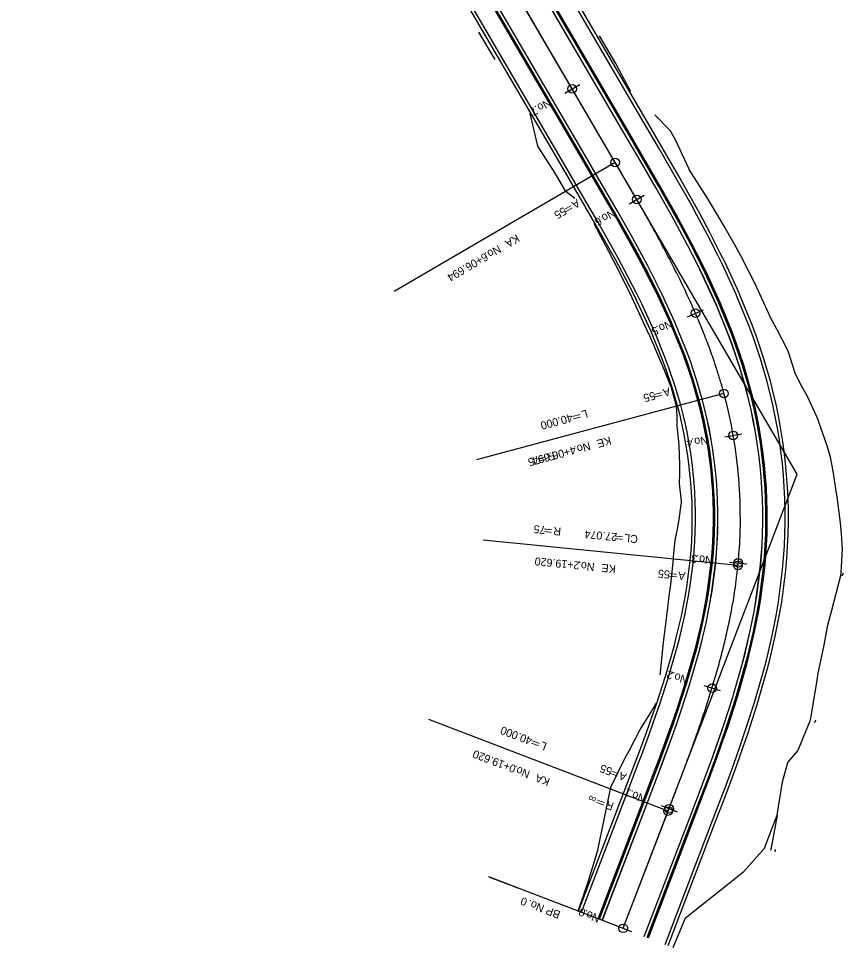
# Model space of a CAD drawing. Extents: x 46424 to 47578, y 10417 to 11548.
# Drawn here: x 46423.8 to 46552.6, y 10417.5 to 10562.5 of the extents above; entities that cross this region are included whole.
import ezdxf

# ---------------------------------------------------------------- set-up
doc = ezdxf.new("R2010")
doc.units = 0
for name, color, linetype in [('Default', 7, 'Continuous'), ('出典（地理院地図Vector）', 7, 'Continuous'), ('河川_人工水路(地下)（地理院地図Vector）', 7, 'Continuous'), ('現況_地形', 7, 'Continuous'), ('現況_地形_三角形', 7, 'Continuous'), ('現況_地形_三角形_頂点', 7, 'Continuous'), ('現況_地形_低い点', 7, 'Continuous'), ('現況_地形_単点標高', 7, 'Continuous'), ('現況_地形_等高線_マイナー', 7, 'Continuous'), ('等高線等深線_等高線_補助曲線通常部（地理院地図Vector）', 7, 'Continuous'), ('設計図面_測点 ラベル メジャー', 7, 'Continuous'), ('設計図面_測点 印 メジャー', 7, 'Continuous')]:
    doc.layers.add(name, color=color, linetype=linetype)

msp = doc.modelspace()

# ---------------------------------------------------------------- linework, layer by layer
at = {"layer": 'Default'}
for p, q in [((46516.96, 10540.04), (46459.34, 10638.67)), ((46510.25, 10551.53), (46510.25, 10551.53)), ((46516.96, 10540.04), (46482.42, 10519.86)), ((46516.96, 10540.04), (46516.96, 10540.04)), ((46520.32, 10534.25), (46520.32, 10534.25)), ((46529.49, 10516.49), (46529.49, 10516.49)), ((46533.94, 10503.96), (46495.3, 10493.6)), ((46533.94, 10503.96), (46495.3, 10493.6)), ((46533.94, 10503.96), (46533.94, 10503.96)), ((46535.38, 10497.42), (46535.38, 10497.42)), ((46536.13, 10477.12), (46496.33, 10481.07)), ((46536.13, 10477.12), (46496.33, 10481.07)), ((46536.13, 10477.12), (46536.13, 10477.12)), ((46536.17, 10477.5), (46536.17, 10477.5)), ((46532.08, 10457.96), (46532.08, 10457.96)), ((46525.23, 10438.76), (46487.88, 10453.07)), ((46525.37, 10439.12), (46525.37, 10439.12)), ((46518.22, 10420.44), (46525.23, 10438.76)), ((46525.23, 10438.76), (46525.23, 10438.76)), ((46517.59, 10420.68), (46497.21, 10428.49)), ((46497.21, 10428.49), (46501.88, 10426.7)), ((46518.22, 10420.44), (46518.22, 10420.44)), ((46518.22, 10420.44), (46518.22, 10420.44))]:
    msp.add_line(p, q, dxfattribs=at)
for centre in [(46510.25, 10551.53), (46516.96, 10540.04), (46520.32, 10534.25), (46529.49, 10516.49), (46533.94, 10503.96), (46535.38, 10497.42), (46536.17, 10477.5), (46536.13, 10477.12), (46532.08, 10457.96), (46525.23, 10438.76), (46525.37, 10439.12), (46518.22, 10420.44), (46518.22, 10420.44)]:
    msp.add_circle(centre, 0.675, dxfattribs=at)
msp.add_arc((46461.5, 10484.53), 75, 354.3288, 15.0122, dxfattribs=at)
for points in [[(46533.94, 10503.96), (46533.81, 10504.42), (46533.56, 10505.34), (46533.01, 10507.16), (46532.27, 10509.42), (46531.3, 10512.11), (46530.24, 10514.76), (46529.11, 10517.39), (46527.92, 10519.98), (46526.67, 10522.55), (46525.37, 10525.1), (46524.03, 10527.62), (46522.66, 10530.13), (46521.26, 10532.62), (46519.84, 10535.1), (46518.64, 10537.16), (46517.68, 10538.8), (46517.2, 10539.63), (46516.96, 10540.04)], [(46525.23, 10438.76), (46525.4, 10439.21), (46525.74, 10440.1), (46526.42, 10441.88), (46527.27, 10444.1), (46528.27, 10446.78), (46529.25, 10449.46), (46530.2, 10452.16), (46531.11, 10454.87), (46531.97, 10457.59), (46532.79, 10460.33), (46533.55, 10463.08), (46534.23, 10465.86), (46534.85, 10468.65), (46535.38, 10471.46), (46535.74, 10473.81), (46535.98, 10475.7), (46536.08, 10476.65), (46536.13, 10477.12)]]:
    msp.add_open_spline(points, degree=3, dxfattribs=at)
at = {"layer": '出典（地理院地図Vector）'}
for points in [[(46541.18, 10505.9), (46540.17, 10509.38), (46539, 10512.84), (46538.39, 10514.51), (46536.37, 10519.48), (46536.36, 10519.5), (46534.16, 10524.29), (46533.37, 10525.89), (46531.8, 10528.97), (46530.16, 10532.05), (46529.34, 10533.53), (46526.83, 10537.98), (46524.29, 10542.35), (46521.77, 10546.67), (46465.82, 10642.45)], [(46526.69, 10502.02), (46525.86, 10504.88), (46524.88, 10507.79), (46524.36, 10509.2), (46522.61, 10513.5), (46522.6, 10513.52), (46520.65, 10517.77), (46519.95, 10519.21), (46518.51, 10522.02), (46516.99, 10524.87), (46516.22, 10526.26), (46513.8, 10530.54), (46511.34, 10534.79), (46508.82, 10539.11), (46452.87, 10634.89)], [(46511.21, 10423.12), (46518.36, 10441.8), (46520.13, 10446.44), (46520.58, 10447.63), (46521.84, 10451.04), (46522.8, 10453.73), (46523.44, 10455.6), (46524.8, 10459.8), (46524.9, 10460.15), (46526.2, 10464.68), (46526.5, 10465.84), (46527.29, 10469.2), (46527.82, 10471.87), (46528.13, 10473.71), (46528.67, 10477.86)], [(46525.22, 10417.76), (46532.37, 10436.44), (46534.17, 10441.14), (46534.63, 10442.37), (46535.94, 10445.92), (46536.96, 10448.79), (46537.65, 10450.79), (46539.13, 10455.38), (46539.25, 10455.77), (46540.7, 10460.85), (46541.04, 10462.17), (46541.95, 10466.05), (46542.57, 10469.17), (46542.95, 10471.37), (46543.59, 10476.38)]]:
    msp.add_lwpolyline(points, dxfattribs=at)
for radius in [82.5, 67.5]:
    msp.add_arc((46461.5, 10484.53), radius, 354.3288, 15.0122, dxfattribs=at)
at = {"layer": '河川_人工水路(地下)（地理院地図Vector）'}
for p, q in [((46516.96, 10540.04), (46459.34, 10638.67)), ((46518.22, 10420.44), (46525.23, 10438.76))]:
    msp.add_line(p, q, dxfattribs=at)
msp.add_arc((46461.5, 10484.53), 75, 354.3288, 15.0122, dxfattribs=at)
for points in [[(46533.94, 10503.96), (46533.81, 10504.42), (46533.56, 10505.34), (46533.01, 10507.16), (46532.27, 10509.42), (46531.3, 10512.11), (46530.24, 10514.76), (46529.11, 10517.39), (46527.92, 10519.98), (46526.67, 10522.55), (46525.37, 10525.1), (46524.03, 10527.62), (46522.66, 10530.13), (46521.26, 10532.62), (46519.84, 10535.1), (46518.64, 10537.16), (46517.68, 10538.8), (46517.2, 10539.63), (46516.96, 10540.04)], [(46525.23, 10438.76), (46525.4, 10439.21), (46525.74, 10440.1), (46526.42, 10441.88), (46527.27, 10444.1), (46528.27, 10446.78), (46529.25, 10449.46), (46530.2, 10452.16), (46531.11, 10454.87), (46531.97, 10457.59), (46532.79, 10460.33), (46533.55, 10463.08), (46534.23, 10465.86), (46534.85, 10468.65), (46535.38, 10471.46), (46535.74, 10473.81), (46535.98, 10475.7), (46536.08, 10476.65), (46536.13, 10477.12)]]:
    msp.add_open_spline(points, degree=3, dxfattribs=at)
at = {"layer": '現況_地形'}
for points in [[(46537.32, 10504.86), (46536.35, 10508.18), (46535.24, 10511.5), (46534.65, 10513.09), (46532.7, 10517.88), (46532.69, 10517.91), (46530.56, 10522.55), (46529.79, 10524.11), (46528.26, 10527.12), (46526.64, 10530.13), (46525.84, 10531.59), (46523.34, 10536.01), (46520.84, 10540.34), (46518.31, 10544.66), (46462.37, 10640.43)], [(46537.33, 10504.87), (46536.36, 10508.18), (46535.25, 10511.5), (46534.66, 10513.1), (46532.71, 10517.89), (46532.7, 10517.91), (46530.57, 10522.56), (46529.8, 10524.12), (46528.26, 10527.12), (46526.65, 10530.14), (46525.85, 10531.6), (46523.35, 10536.02), (46520.85, 10540.34), (46518.32, 10544.66), (46462.38, 10640.44)], [(46530.55, 10503.05), (46529.66, 10506.08), (46528.64, 10509.14), (46528.09, 10510.61), (46526.27, 10515.09), (46526.26, 10515.11), (46524.25, 10519.5), (46523.52, 10520.99), (46522.05, 10523.87), (46520.49, 10526.78), (46519.71, 10528.19), (46517.26, 10532.52), (46514.78, 10536.8), (46512.26, 10541.12), (46456.31, 10636.9)], [(46530.56, 10503.05), (46529.67, 10506.08), (46528.65, 10509.14), (46528.1, 10510.62), (46526.28, 10515.09), (46526.27, 10515.12), (46524.25, 10519.51), (46523.53, 10520.99), (46522.05, 10523.87), (46520.5, 10526.78), (46519.72, 10528.2), (46517.27, 10532.53), (46514.79, 10536.81), (46512.27, 10541.13), (46456.32, 10636.9)], [(46514.94, 10421.7), (46522.09, 10440.37), (46523.86, 10445.03), (46524.31, 10446.23), (46525.59, 10449.68), (46526.56, 10452.42), (46527.22, 10454.32), (46528.61, 10458.63), (46528.72, 10458.98), (46530.06, 10463.66), (46530.37, 10464.87), (46531.19, 10468.36), (46531.74, 10471.15), (46532.07, 10473.09), (46532.64, 10477.47)], [(46514.95, 10421.69), (46522.1, 10440.37), (46523.87, 10445.03), (46524.32, 10446.22), (46525.6, 10449.67), (46526.57, 10452.42), (46527.23, 10454.32), (46528.62, 10458.62), (46528.73, 10458.98), (46530.07, 10463.66), (46530.38, 10464.87), (46531.2, 10468.36), (46531.75, 10471.15), (46532.08, 10473.09), (46532.65, 10477.47)], [(46521.49, 10419.19), (46528.64, 10437.87), (46530.42, 10442.56), (46530.88, 10443.77), (46532.18, 10447.29), (46533.18, 10450.11), (46533.86, 10452.08), (46535.31, 10456.56), (46535.43, 10456.93), (46536.83, 10461.87), (46537.17, 10463.15), (46538.04, 10466.89), (46538.64, 10469.89), (46538.99, 10471.99), (46539.61, 10476.77)], [(46521.5, 10419.19), (46528.65, 10437.86), (46530.43, 10442.55), (46530.89, 10443.77), (46532.19, 10447.28), (46533.19, 10450.1), (46533.87, 10452.07), (46535.32, 10456.56), (46535.43, 10456.93), (46536.84, 10461.87), (46537.18, 10463.15), (46538.05, 10466.89), (46538.65, 10469.89), (46539, 10471.99), (46539.62, 10476.77)]]:
    msp.add_lwpolyline(points, dxfattribs=at)
for radius in [78.5, 78.51, 71.49, 71.5]:
    msp.add_arc((46461.5, 10484.53), radius, 354.3288, 15.0122, dxfattribs=at)
at = {"layer": '現況_地形_三角形'}
msp.add_line((46498.23, 10556.09), (46495.64, 10560.37), dxfattribs=at)
for points in [[(46519.38, 10551.07), (46517.07, 10555.51), (46514.51, 10559.8)], [(46510.66, 10534.4), (46509.23, 10535.52), (46507.56, 10538.37), (46504.85, 10542.58), (46503.7, 10547.7)], [(46511.19, 10423.13), (46512.79, 10427.87), (46514.24, 10432.67), (46516.21, 10442.22), (46516.33, 10442.58), (46518.52, 10447.05), (46519.15, 10448.16), (46520.8, 10451.41), (46522.35, 10453.89), (46523.39, 10455.62)]]:
    msp.add_lwpolyline(points, dxfattribs=at)
at = {"layer": '現況_地形_三角形_頂点'}
for p, q in [((46552.41, 10475.5), (46552.59, 10475.95)), ((46548.15, 10452.6), (46548.3, 10453)), ((46541.96, 10432.36), (46542, 10432.75))]:
    msp.add_line(p, q, dxfattribs=at)
for points in [[(46526.01, 10417.46), (46527.93, 10422.08), (46532.48, 10425.69), (46537.03, 10429.3), (46540.31, 10432.99), (46540.45, 10433.35), (46542.26, 10438.09), (46542.46, 10439.43), (46543.08, 10443.34), (46543.9, 10446.36), (46545.45, 10448.15), (46547.4, 10452.84), (46547.52, 10453.24), (46548.43, 10458.81), (46548.65, 10460.26), (46549.53, 10464.42), (46550.15, 10467.79), (46550.78, 10470.13), (46552.2, 10475.52), (46552.24, 10475.98), (46552.45, 10479.63), (46552.3, 10482.06), (46552.15, 10483.74), (46551.63, 10487.81), (46551.58, 10488.08), (46550.99, 10491.84), (46550.58, 10494.02), (46550.03, 10495.8), (46548.7, 10499.66), (46548.71, 10499.75), (46547.03, 10503.38), (46546.05, 10505.17), (46545.13, 10506.96), (46543.97, 10510.57), (46542.21, 10513.99), (46541.3, 10515.6), (46539.03, 10520.63), (46539.02, 10520.66), (46536.57, 10525.46), (46535.7, 10527.05), (46533.97, 10530.11), (46532.16, 10533.14), (46531.27, 10534.6), (46528.53, 10538.96), (46528.52, 10538.99), (46526.35, 10543.55), (46525.53, 10545.05), (46523.14, 10547.47)], [(46524, 10460.05), (46524.04, 10460.41), (46524.48, 10465.13), (46524.65, 10466.31), (46525.09, 10469.67), (46525.37, 10472.31), (46525.63, 10474.11), (46526.04, 10478.12), (46526.06, 10478.45), (46526.34, 10481.04), (46526.66, 10482.76), (46526.87, 10483.96), (46527.32, 10486.93), (46527.3, 10487.13), (46527.02, 10489.88), (46527.05, 10491.51), (46527.04, 10492.88), (46526.95, 10495.89), (46526.95, 10495.95), (46526.65, 10498.89), (46526.61, 10500.43), (46526.54, 10501.98), (46525.74, 10504.85), (46524.6, 10507.69), (46524.01, 10509.07), (46522.19, 10513.31), (46522.18, 10513.34), (46520.22, 10517.56), (46519.54, 10519.01), (46518.17, 10521.84), (46516.71, 10524.72), (46515.98, 10526.13), (46513.69, 10530.47)], [(46541.25, 10432.63), (46541.38, 10432.99), (46542.28, 10438.08)]]:
    msp.add_lwpolyline(points, dxfattribs=at)
at = {"layer": '現況_地形_低い点'}
for points in [[(46537.8, 10504.99), (46536.83, 10508.33), (46535.71, 10511.66), (46535.12, 10513.27), (46533.16, 10518.08), (46533.15, 10518.11), (46531.01, 10522.77), (46530.24, 10524.33), (46528.7, 10527.35), (46527.08, 10530.37), (46526.28, 10531.83), (46523.78, 10536.26), (46521.27, 10540.59), (46518.75, 10544.91), (46462.8, 10640.69)], [(46530.07, 10502.92), (46529.2, 10505.93), (46528.18, 10508.97), (46527.64, 10510.44), (46525.82, 10514.89), (46525.81, 10514.92), (46523.8, 10519.29), (46523.08, 10520.77), (46521.61, 10523.64), (46520.06, 10526.54), (46519.28, 10527.96), (46516.84, 10532.28), (46514.36, 10536.56), (46511.84, 10540.87), (46455.89, 10636.65)], [(46514.48, 10421.87), (46521.63, 10440.55), (46523.41, 10445.2), (46523.86, 10446.4), (46525.13, 10449.84), (46526.1, 10452.58), (46526.75, 10454.48), (46528.14, 10458.77), (46528.25, 10459.12), (46529.58, 10463.79), (46529.89, 10464.99), (46530.71, 10468.47), (46531.26, 10471.24), (46531.59, 10473.16), (46532.15, 10477.51)], [(46521.95, 10419.01), (46529.1, 10437.69), (46530.89, 10442.38), (46531.35, 10443.59), (46532.65, 10447.12), (46533.65, 10449.94), (46534.33, 10451.92), (46535.79, 10456.41), (46535.9, 10456.79), (46537.32, 10461.74), (46537.65, 10463.03), (46538.53, 10466.78), (46539.13, 10469.8), (46539.49, 10471.91), (46540.11, 10476.72)]]:
    msp.add_lwpolyline(points, dxfattribs=at)
for radius in [79, 71]:
    msp.add_arc((46461.5, 10484.53), radius, 354.3288, 15.0122, dxfattribs=at)
at = {"layer": '現況_地形_単点標高'}
for points in [[(46540.7, 10505.77), (46539.69, 10509.23), (46538.53, 10512.67), (46537.93, 10514.33), (46535.91, 10519.28), (46535.9, 10519.3), (46533.71, 10524.08), (46532.93, 10525.67), (46531.36, 10528.74), (46529.72, 10531.81), (46528.9, 10533.29), (46526.39, 10537.73), (46523.86, 10542.1), (46521.34, 10546.42), (46465.39, 10642.2)], [(46537.99, 10505.05), (46537.02, 10508.39), (46535.9, 10511.73), (46535.31, 10513.34), (46533.35, 10518.16), (46533.33, 10518.19), (46531.19, 10522.86), (46530.42, 10524.42), (46528.88, 10527.44), (46527.26, 10530.47), (46526.46, 10531.93), (46523.95, 10536.36), (46521.44, 10540.69), (46518.92, 10545.01), (46462.97, 10640.79)], [(46529.88, 10502.87), (46529.01, 10505.87), (46527.99, 10508.9), (46527.45, 10510.37), (46525.64, 10514.81), (46525.63, 10514.84), (46523.62, 10519.2), (46522.9, 10520.68), (46521.43, 10523.55), (46519.88, 10526.45), (46519.11, 10527.86), (46516.67, 10532.18), (46514.19, 10536.46), (46511.67, 10540.77), (46455.72, 10636.55)], [(46527.18, 10502.14), (46526.33, 10505.03), (46525.35, 10507.96), (46524.83, 10509.38), (46523.07, 10513.7), (46523.06, 10513.72), (46521.1, 10517.98), (46520.39, 10519.43), (46518.95, 10522.25), (46517.42, 10525.11), (46516.66, 10526.5), (46514.24, 10530.79), (46511.77, 10535.05), (46509.25, 10539.36), (46453.3, 10635.14)], [(46511.68, 10422.94), (46518.83, 10441.62), (46520.6, 10446.26), (46521.05, 10447.45), (46522.31, 10450.86), (46523.27, 10453.57), (46523.91, 10455.44), (46525.28, 10459.65), (46525.38, 10460), (46526.68, 10464.55), (46526.98, 10465.72), (46527.77, 10469.1), (46528.31, 10471.78), (46528.62, 10473.63), (46529.16, 10477.81)], [(46514.3, 10421.94), (46521.45, 10440.62), (46523.22, 10445.27), (46523.67, 10446.47), (46524.94, 10449.91), (46525.91, 10452.65), (46526.56, 10454.54), (46527.95, 10458.83), (46528.06, 10459.18), (46529.39, 10463.84), (46529.7, 10465.04), (46530.51, 10468.51), (46531.06, 10471.27), (46531.39, 10473.2), (46531.95, 10477.53)], [(46522.14, 10418.94), (46529.29, 10437.62), (46531.08, 10442.31), (46531.53, 10443.52), (46532.84, 10447.05), (46533.84, 10449.88), (46534.52, 10451.85), (46535.98, 10456.36), (46536.09, 10456.73), (46537.51, 10461.69), (46537.84, 10462.98), (46538.72, 10466.74), (46539.33, 10469.77), (46539.69, 10471.88), (46540.31, 10476.7)], [(46524.76, 10417.94), (46531.91, 10436.62), (46533.7, 10441.32), (46534.16, 10442.54), (46535.47, 10446.09), (46536.49, 10448.95), (46537.17, 10450.95), (46538.66, 10455.53), (46538.77, 10455.91), (46540.22, 10460.98), (46540.56, 10462.3), (46541.46, 10466.15), (46542.08, 10469.26), (46542.45, 10471.44), (46543.1, 10476.43)]]:
    msp.add_lwpolyline(points, dxfattribs=at)
for radius in [82, 79.2, 70.8, 68]:
    msp.add_arc((46461.5, 10484.53), radius, 354.3288, 15.0122, dxfattribs=at)
at = {"layer": '現況_地形_等高線_マイナー'}
for points in [[(46537.82, 10505), (46536.85, 10508.34), (46535.73, 10511.67), (46535.14, 10513.28), (46533.18, 10518.09), (46533.17, 10518.11), (46531.03, 10522.78), (46530.26, 10524.34), (46528.72, 10527.36), (46527.1, 10530.38), (46526.3, 10531.84), (46523.79, 10536.27), (46521.29, 10540.6), (46518.76, 10544.92), (46462.82, 10640.7)], [(46530.05, 10502.92), (46529.18, 10505.93), (46528.16, 10508.96), (46527.62, 10510.43), (46525.81, 10514.88), (46525.8, 10514.91), (46523.79, 10519.28), (46523.06, 10520.76), (46521.59, 10523.63), (46520.04, 10526.53), (46519.26, 10527.95), (46516.82, 10532.27), (46514.34, 10536.55), (46511.82, 10540.86), (46455.87, 10636.64)], [(46514.46, 10421.88), (46521.61, 10440.56), (46523.39, 10445.21), (46523.84, 10446.41), (46525.11, 10449.85), (46526.08, 10452.59), (46526.73, 10454.49), (46528.12, 10458.78), (46528.23, 10459.13), (46529.56, 10463.79), (46529.87, 10464.99), (46530.69, 10468.47), (46531.24, 10471.24), (46531.57, 10473.17), (46532.13, 10477.52)], [(46521.97, 10419), (46529.12, 10437.68), (46530.91, 10442.37), (46531.37, 10443.59), (46532.67, 10447.11), (46533.67, 10449.94), (46534.35, 10451.91), (46535.81, 10456.41), (46535.92, 10456.78), (46537.34, 10461.74), (46537.67, 10463.03), (46538.55, 10466.78), (46539.15, 10469.8), (46539.51, 10471.91), (46540.13, 10476.72)]]:
    msp.add_lwpolyline(points, dxfattribs=at)
for radius in [79.02, 70.98]:
    msp.add_arc((46461.5, 10484.53), radius, 354.3288, 15.0122, dxfattribs=at)
at = {"layer": '等高線等深線_等高線_補助曲線通常部（地理院地図Vector）'}
for p, q in [((46545.38, 10491.38), (46423.8, 10699.52)), ((46516.96, 10540.04), (46459.34, 10638.67)), ((46518.22, 10420.44), (46545.38, 10491.38)), ((46518.22, 10420.44), (46525.23, 10438.76))]:
    msp.add_line(p, q, dxfattribs=at)
msp.add_arc((46461.5, 10484.53), 75, 354.3288, 15.0122, dxfattribs=at)
msp.add_arc((46461.5, 10484.53), 75, 354.3288, 15.0122, dxfattribs=at)
for points in [[(46533.94, 10503.96), (46533.81, 10504.42), (46533.56, 10505.34), (46533.01, 10507.16), (46532.27, 10509.42), (46531.3, 10512.11), (46530.24, 10514.76), (46529.11, 10517.39), (46527.92, 10519.98), (46526.67, 10522.55), (46525.37, 10525.1), (46524.03, 10527.62), (46522.66, 10530.13), (46521.26, 10532.62), (46519.84, 10535.1), (46518.64, 10537.16), (46517.68, 10538.8), (46517.2, 10539.63), (46516.96, 10540.04)], [(46533.94, 10503.96), (46533.81, 10504.42), (46533.56, 10505.34), (46533.01, 10507.16), (46532.27, 10509.42), (46531.3, 10512.11), (46530.24, 10514.76), (46529.11, 10517.39), (46527.92, 10519.98), (46526.67, 10522.55), (46525.37, 10525.1), (46524.03, 10527.62), (46522.66, 10530.13), (46521.26, 10532.62), (46519.84, 10535.1), (46518.64, 10537.16), (46517.68, 10538.8), (46517.2, 10539.63), (46516.96, 10540.04)], [(46525.23, 10438.76), (46525.4, 10439.21), (46525.74, 10440.1), (46526.42, 10441.88), (46527.27, 10444.1), (46528.27, 10446.78), (46529.25, 10449.46), (46530.2, 10452.16), (46531.11, 10454.87), (46531.97, 10457.59), (46532.79, 10460.33), (46533.55, 10463.08), (46534.23, 10465.86), (46534.85, 10468.65), (46535.38, 10471.46), (46535.74, 10473.81), (46535.98, 10475.7), (46536.08, 10476.65), (46536.13, 10477.12)], [(46525.23, 10438.76), (46525.4, 10439.21), (46525.74, 10440.1), (46526.42, 10441.88), (46527.27, 10444.1), (46528.27, 10446.78), (46529.25, 10449.46), (46530.2, 10452.16), (46531.11, 10454.87), (46531.97, 10457.59), (46532.79, 10460.33), (46533.55, 10463.08), (46534.23, 10465.86), (46534.85, 10468.65), (46535.38, 10471.46), (46535.74, 10473.81), (46535.98, 10475.7), (46536.08, 10476.65), (46536.13, 10477.12)]]:
    msp.add_open_spline(points, degree=3, dxfattribs=at)
at = {"layer": '設計図面_測点 印 メジャー'}
for p, q in [((46509.08, 10550.84), (46511.41, 10552.21)), ((46519.15, 10533.58), (46521.49, 10534.92)), ((46528.26, 10515.95), (46530.73, 10517.02)), ((46534.05, 10497.19), (46536.71, 10497.66)), ((46534.82, 10477.62), (46537.51, 10477.37)), ((46530.79, 10458.35), (46533.37, 10457.56)), ((46524.11, 10439.6), (46526.63, 10438.64)), ((46516.96, 10420.92), (46519.48, 10419.96))]:
    msp.add_line(p, q, dxfattribs=at)

# ---------------------------------------------------------------- texts
at = {"layer": 'Default'}
for s, rotation, p in [('A＝', 210.291, (46510.98, 10534.37)), ('55', 210.291, (46508.88, 10533.14)), ('KA', 210.291, (46501.55, 10528.87)), ('\u3000No.', 210.291, (46500.15, 10528.05)), ('6+06.694', 210.291, (46496.64, 10526)), ('55', 195.0122, (46523.03, 10504.27)), ('A＝', 195.0122, (46525.38, 10504.9)), ('L＝', 195.0122, (46512.48, 10501.44)), ('40.000', 195.0122, (46510.13, 10500.81)), ('KE', 195.0122, (46516.13, 10497.24)), ('4+06.694', 195.0122, (46510.64, 10495.77)), ('\u3000No.', 195.0122, (46514.56, 10496.82)), ('75', 195.0122, (46505.01, 10494.26)), ('R＝', 195.0122, (46507.36, 10494.89)), ('75', 174.3288, (46506.13, 10483.24)), ('R＝', 174.3288, (46508.56, 10483)), ('27.074', 174.3288, (46517.32, 10482.13)), ('CL＝', 174.3288, (46520.55, 10481.81)), ('2+19.620', 174.3288, (46511.44, 10477.69)), ('\u3000No.', 174.3288, (46515.48, 10477.29)), ('KE', 174.3288, (46517.1, 10477.13)), ('55', 174.3288, (46525.54, 10476.29)), ('A＝', 174.3288, (46527.97, 10476.05)), ('40.000', 159.05, (46504.11, 10450.2)), ('L＝', 159.05, (46506.39, 10449.33)), ('0+19.620', 159.05, (46501.57, 10445.82)), ('\u3000No.', 159.05, (46505.36, 10444.37)), ('55', 159.05, (46516.59, 10445.42)), ('A＝', 159.05, (46518.86, 10444.55)), ('KA', 159.05, (46506.87, 10443.79)), ('R＝∞', 159.05, (46516.85, 10439.96)), ('0', 159.05, (46503.35, 10425.04)), ('BP No.', 159.05, (46508.51, 10423.06))]:
    msp.add_text(s, height=1.25, rotation=rotation, dxfattribs=at).set_placement(p)
at = {"layer": '設計図面_測点 ラベル メジャー'}
for s, rotation, p in [('No.', 210.291, (46506.48, 10550.05)), ('7', 210.291, (46504.38, 10548.82)), ('No.', 209.8631, (46516.54, 10532.8)), ('6', 209.8631, (46514.43, 10531.58)), ('5', 203.4864, (46523.34, 10514.49)), ('No.', 203.4864, (46525.58, 10515.47)), ('No.', 189.8981, (46531.33, 10497.35)), ('4', 189.8981, (46528.93, 10496.93)), ('3', 174.6193, (46529.82, 10478.72)), ('No.', 174.6193, (46532.24, 10478.5)), ('2', 163.0163, (46526.1, 10460.43)), ('No.', 163.0163, (46528.43, 10459.72)), ('1', 159.0513, (46519.58, 10442)), ('No.', 159.0513, (46521.86, 10441.13)), ('0', 159.05, (46512.43, 10423.33)), ('No.', 159.05, (46514.71, 10422.45))]:
    msp.add_text(s, height=1.25, rotation=rotation, dxfattribs=at).set_placement(p)

doc.saveas('drawing.dxf')
